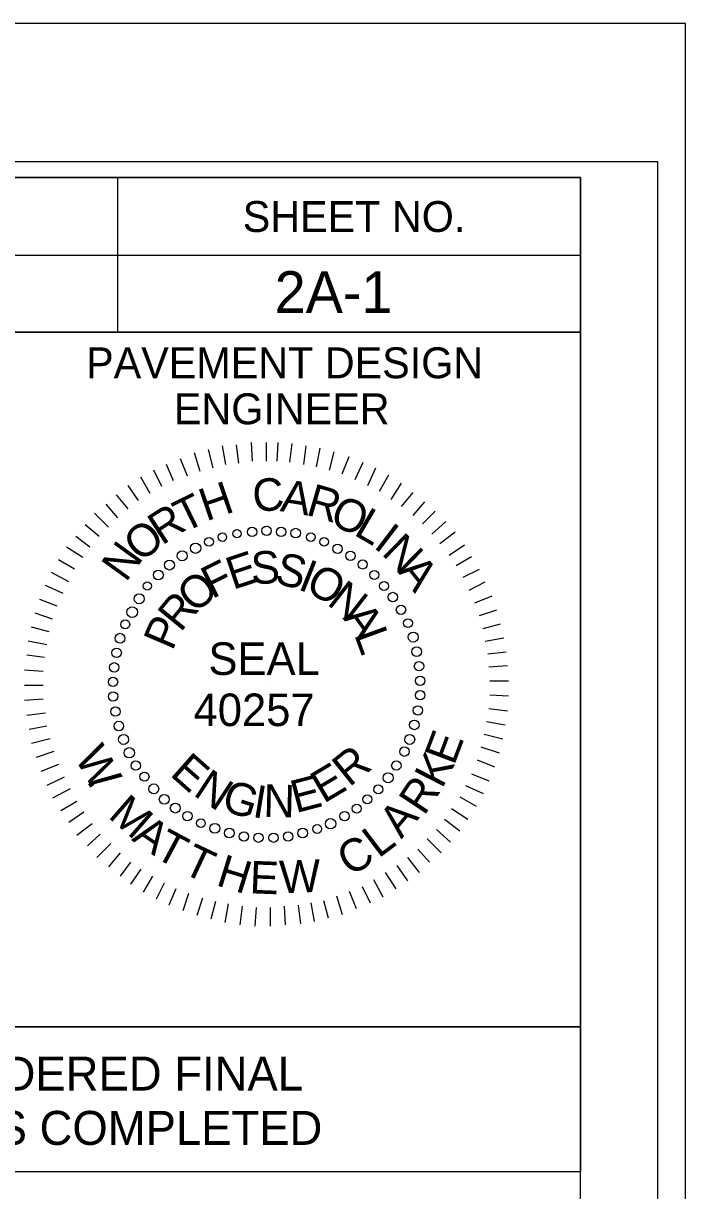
# Model space of a CAD drawing. Extents: x 2137858 to 2138172, y 2136084 to 2136289.
# Drawn here: x 2138152.47 to 2138172.48, y 2136253.7 to 2136289.01 of the extents above; entities that cross this region are included whole.
import ezdxf

# ---------------------------------------------------------------- set-up
doc = ezdxf.new("R2010")
doc.units = 0
for name, color, linetype in [('Default', 7, 'Continuous'), ('Sheet Cutting Line CELL', 7, 'Continuous'), ('Sheet Data Field CELL', 7, 'Continuous'), ('Sheet Plot Border Inside CELL', 7, 'Continuous'), ('Sheet Plot Border Outside CELL', 7, 'Continuous'), ('Sheet Sticker Exception Certification CELL', 7, 'Continuous'), ('Sheet Typical CELL', 7, 'Continuous')]:
    doc.layers.add(name, color=color, linetype=linetype)

msp = doc.modelspace()

# ---------------------------------------------------------------- linework, layer by layer
at = {"layer": 'Default'}
for p, q in [((2138159.889, 2136278.05), (2138159.889, 2136278.05)), ((2138159.398, 2136275.77), (2138159.363, 2136276.333)), ((2138159.82, 2136275.77), (2138159.82, 2136276.333)), ((2138160.136, 2136275.77), (2138160.172, 2136276.333)), ((2138160.523, 2136275.735), (2138160.593, 2136276.297)), ((2138157.816, 2136275.454), (2138157.64, 2136276.016)), ((2138158.203, 2136275.559), (2138158.062, 2136276.122)), ((2138158.589, 2136275.665), (2138158.484, 2136276.227)), ((2138158.976, 2136275.7), (2138158.906, 2136276.262)), ((2138160.945, 2136275.665), (2138161.015, 2136276.227)), ((2138161.332, 2136275.594), (2138161.437, 2136276.157)), ((2138161.718, 2136275.489), (2138161.859, 2136276.051)), ((2138157.007, 2136275.172), (2138156.797, 2136275.665)), ((2138157.429, 2136275.313), (2138157.218, 2136275.84)), ((2138162.105, 2136275.383), (2138162.316, 2136275.911)), ((2138162.492, 2136275.208), (2138162.738, 2136275.735)), ((2138156.304, 2136274.786), (2138156.023, 2136275.278)), ((2138156.656, 2136274.997), (2138156.41, 2136275.489)), ((2138162.879, 2136275.032), (2138163.125, 2136275.559)), ((2138163.23, 2136274.856), (2138163.511, 2136275.348)), ((2138155.953, 2136274.575), (2138155.636, 2136275.032)), ((2138163.582, 2136274.61), (2138163.898, 2136275.102)), ((2138155.636, 2136274.329), (2138155.285, 2136274.751)), ((2138163.898, 2136274.399), (2138164.25, 2136274.821)), ((2138164.25, 2136274.118), (2138164.601, 2136274.54)), ((2138155.039, 2136273.766), (2138154.617, 2136274.188)), ((2138155.32, 2136274.047), (2138154.968, 2136274.469)), ((2138164.531, 2136273.872), (2138164.918, 2136274.258)), ((2138154.757, 2136273.485), (2138154.336, 2136273.837)), ((2138164.812, 2136273.555), (2138165.234, 2136273.942)), ((2138154.476, 2136273.169), (2138154.054, 2136273.485)), ((2138165.058, 2136273.274), (2138165.515, 2136273.626)), ((2138154.265, 2136272.852), (2138153.773, 2136273.169)), ((2138165.34, 2136272.922), (2138165.797, 2136273.239)), ((2138154.019, 2136272.501), (2138153.527, 2136272.782)), ((2138165.55, 2136272.606), (2138166.008, 2136272.887)), ((2138165.761, 2136272.254), (2138166.254, 2136272.501)), ((2138153.843, 2136272.114), (2138153.316, 2136272.395)), ((2138165.937, 2136271.868), (2138166.429, 2136272.114)), ((2138153.668, 2136271.762), (2138153.14, 2136272.008)), ((2138166.113, 2136271.481), (2138166.64, 2136271.692)), ((2138153.492, 2136271.376), (2138152.964, 2136271.587)), ((2138153.351, 2136270.989), (2138152.824, 2136271.165)), ((2138166.254, 2136271.094), (2138166.781, 2136271.27)), ((2138153.246, 2136270.602), (2138152.718, 2136270.743)), ((2138166.359, 2136270.708), (2138166.886, 2136270.848)), ((2138153.175, 2136270.215), (2138152.613, 2136270.321)), ((2138166.429, 2136270.321), (2138166.992, 2136270.426)), ((2138166.5, 2136269.934), (2138167.062, 2136270.004)), ((2138153.105, 2136269.829), (2138152.578, 2136269.899)), ((2138166.535, 2136269.547), (2138167.097, 2136269.583)), ((2138153.07, 2136269.407), (2138152.507, 2136269.442)), ((2138153.07, 2136268.985), (2138152.507, 2136268.985)), ((2138159.82, 2136269.02), (2138159.82, 2136269.02)), ((2138166.57, 2136269.126), (2138167.133, 2136269.126)), ((2138153.07, 2136268.563), (2138152.507, 2136268.528)), ((2138166.57, 2136268.704), (2138167.133, 2136268.669)), ((2138166.535, 2136268.282), (2138167.097, 2136268.212)), ((2138153.14, 2136268.141), (2138152.578, 2136268.071)), ((2138166.465, 2136267.895), (2138167.027, 2136267.79)), ((2138153.175, 2136267.754), (2138152.648, 2136267.649)), ((2138166.394, 2136267.508), (2138166.957, 2136267.368)), ((2138153.281, 2136267.368), (2138152.718, 2136267.227)), ((2138166.289, 2136267.122), (2138166.851, 2136266.946)), ((2138153.386, 2136266.981), (2138152.859, 2136266.805)), ((2138153.527, 2136266.594), (2138153, 2136266.383)), ((2138166.183, 2136266.735), (2138166.711, 2136266.524)), ((2138153.703, 2136266.208), (2138153.175, 2136265.962)), ((2138166.008, 2136266.313), (2138166.535, 2136266.102)), ((2138153.879, 2136265.856), (2138153.351, 2136265.575)), ((2138165.832, 2136265.962), (2138166.359, 2136265.715)), ((2138154.089, 2136265.469), (2138153.597, 2136265.188)), ((2138165.656, 2136265.61), (2138166.148, 2136265.329)), ((2138154.3, 2136265.153), (2138153.843, 2136264.836)), ((2138165.41, 2136265.258), (2138165.902, 2136264.942)), ((2138154.546, 2136264.801), (2138154.089, 2136264.45)), ((2138165.199, 2136264.942), (2138165.656, 2136264.59)), ((2138154.793, 2136264.485), (2138154.406, 2136264.133)), ((2138164.672, 2136264.344), (2138165.093, 2136263.922)), ((2138164.953, 2136264.626), (2138165.375, 2136264.239)), ((2138155.109, 2136264.204), (2138154.687, 2136263.782)), ((2138164.39, 2136264.028), (2138164.742, 2136263.641)), ((2138155.39, 2136263.922), (2138155.039, 2136263.501)), ((2138155.707, 2136263.641), (2138155.39, 2136263.219)), ((2138164.074, 2136263.782), (2138164.425, 2136263.325)), ((2138156.023, 2136263.43), (2138155.707, 2136262.973)), ((2138156.375, 2136263.219), (2138156.093, 2136262.727)), ((2138163.406, 2136263.325), (2138163.722, 2136262.833)), ((2138163.758, 2136263.536), (2138164.074, 2136263.079)), ((2138156.726, 2136263.008), (2138156.48, 2136262.516)), ((2138162.703, 2136262.903), (2138162.949, 2136262.411)), ((2138163.054, 2136263.114), (2138163.336, 2136262.586)), ((2138157.078, 2136262.833), (2138156.867, 2136262.34)), ((2138157.464, 2136262.692), (2138157.289, 2136262.165)), ((2138157.886, 2136262.551), (2138157.711, 2136262.024)), ((2138161.929, 2136262.622), (2138162.105, 2136262.059)), ((2138162.316, 2136262.762), (2138162.527, 2136262.235)), ((2138158.273, 2136262.446), (2138158.132, 2136261.918)), ((2138158.66, 2136262.376), (2138158.554, 2136261.813)), ((2138159.082, 2136262.305), (2138159.011, 2136261.743)), ((2138159.504, 2136262.27), (2138159.468, 2136261.708)), ((2138159.925, 2136262.27), (2138159.925, 2136261.708)), ((2138160.347, 2136262.305), (2138160.382, 2136261.743)), ((2138160.769, 2136262.34), (2138160.839, 2136261.778)), ((2138161.156, 2136262.411), (2138161.261, 2136261.848)), ((2138161.543, 2136262.481), (2138161.683, 2136261.954))]:
    msp.add_line(p, q, dxfattribs=at)
for centre, radius in [((2138158.08, 2136273.327), 0.134), ((2138158.484, 2136273.467), 0.128), ((2138158.923, 2136273.573), 0.124), ((2138159.381, 2136273.626), 0.142), ((2138159.82, 2136273.661), 0.141), ((2138160.259, 2136273.626), 0.142), ((2138160.699, 2136273.59), 0.145), ((2138161.156, 2136273.467), 0.128), ((2138161.56, 2136273.327), 0.134), ((2138157.675, 2136273.133), 0.157), ((2138161.965, 2136273.116), 0.142), ((2138156.884, 2136272.624), 0.151), ((2138157.271, 2136272.905), 0.151), ((2138162.351, 2136272.905), 0.142), ((2138162.72, 2136272.641), 0.137), ((2138156.55, 2136272.325), 0.149), ((2138163.072, 2136272.325), 0.137), ((2138156.216, 2136271.991), 0.124), ((2138163.371, 2136271.991), 0.137), ((2138155.97, 2136271.604), 0.151), ((2138163.634, 2136271.657), 0.142), ((2138155.759, 2136271.2), 0.162), ((2138163.881, 2136271.27), 0.142), ((2138164.091, 2136270.866), 0.134), ((2138155.548, 2136270.831), 0.134), ((2138155.39, 2136270.409), 0.15), ((2138164.25, 2136270.444), 0.15), ((2138155.285, 2136269.969), 0.145), ((2138164.355, 2136270.004), 0.145), ((2138155.214, 2136269.53), 0.142), ((2138164.425, 2136269.565), 0.142), ((2138155.179, 2136269.09), 0.141), ((2138164.461, 2136269.126), 0.141), ((2138155.179, 2136268.651), 0.142), ((2138164.461, 2136268.686), 0.142), ((2138155.25, 2136268.194), 0.142), ((2138164.39, 2136268.229), 0.142), ((2138155.355, 2136267.754), 0.145), ((2138164.285, 2136267.79), 0.145), ((2138155.496, 2136267.35), 0.15), ((2138164.144, 2136267.35), 0.15), ((2138155.671, 2136266.946), 0.157), ((2138163.986, 2136266.981), 0.142), ((2138155.865, 2136266.559), 0.142), ((2138163.74, 2136266.559), 0.142), ((2138156.129, 2136266.225), 0.137), ((2138163.494, 2136266.19), 0.151), ((2138156.41, 2136265.856), 0.149), ((2138156.726, 2136265.54), 0.149), ((2138163.195, 2136265.838), 0.137), ((2138157.06, 2136265.276), 0.151), ((2138162.545, 2136265.258), 0.137), ((2138162.861, 2136265.54), 0.137), ((2138157.429, 2136265.03), 0.142), ((2138162.175, 2136265.03), 0.142), ((2138157.834, 2136264.819), 0.134), ((2138158.255, 2136264.661), 0.15), ((2138158.695, 2136264.52), 0.145), ((2138160.91, 2136264.52), 0.145), ((2138161.349, 2136264.643), 0.134), ((2138161.754, 2136264.801), 0.157), ((2138159.134, 2136264.415), 0.142), ((2138159.574, 2136264.379), 0.141), ((2138160.031, 2136264.379), 0.141), ((2138160.47, 2136264.415), 0.142)]:
    msp.add_circle(centre, radius, dxfattribs=at)
at = {"layer": 'Sheet Cutting Line CELL'}
msp.add_line((2138172.482, 2136289.006), (2137858.136, 2136289.006), dxfattribs=at)
at = {"layer": 'Sheet Plot Border Inside CELL'}
msp.add_lwpolyline([(2138171.642, 2136284.815), (2137860.562, 2136284.815), (2137860.562, 2136087.863), (2138171.642, 2136087.863)], close=True, dxfattribs=at)
at = {"layer": 'Sheet Plot Border Outside CELL'}
msp.add_lwpolyline([(2138172.482, 2136289.006), (2137858.136, 2136289.006), (2137858.136, 2136083.673), (2138172.482, 2136083.673)], close=True, dxfattribs=at)
at = {"layer": 'Sheet Sticker Exception Certification CELL'}
for p, q in [((2138131.966, 2136258.663), (2138169.309, 2136258.663)), ((2138169.309, 2136258.661), (2138169.309, 2136254.274)), ((2138169.309, 2136254.276), (2138131.966, 2136254.276))]:
    msp.add_line(p, q, dxfattribs=at)
at = {"layer": 'Sheet Typical CELL'}
for p, q in [((2138155.309, 2136284.33), (2138155.309, 2136279.663)), ((2138131.966, 2136281.997), (2138169.309, 2136281.997))]:
    msp.add_line(p, q, dxfattribs=at)
for points in [[(2138169.309, 2136284.339), (2137889.309, 2136284.339), (2137889.309, 2136088.339), (2138169.309, 2136088.339)], [(2138131.966, 2136284.339), (2138169.309, 2136284.339), (2138169.309, 2136279.663), (2138131.966, 2136279.663)], [(2138150.642, 2136279.663), (2138169.309, 2136279.663), (2138169.309, 2136258.663), (2138150.642, 2136258.663)]]:
    msp.add_lwpolyline(points, close=True, dxfattribs=at)

# ---------------------------------------------------------------- texts
at = {"layer": 'Default'}
for s, rotation, p in [('C', 4.8625, (2138159.433, 2136274.223)), ('H', 18.9162, (2138157.992, 2136273.942)), ('A', 350.8088, (2138160.207, 2136274.258)), ('R', 343.7819, (2138160.98, 2136274.153)), ('T', 25.943, (2138157.324, 2136273.59)), ('O', 336.7551, (2138161.683, 2136273.872)), ('R', 32.9699, (2138156.656, 2136273.204)), ('L', 329.7282, (2138162.422, 2136273.555)), ('O', 39.9967, (2138156.023, 2136272.676)), ('I', 322.7014, (2138163.019, 2136273.169)), ('N', 315.6745, (2138163.265, 2136272.958)), ('N', 54.0504, (2138155.566, 2136272.079)), ('F', 26.4777, (2138158.168, 2136271.587)), ('E', 18.4448, (2138158.8, 2136271.868)), ('S', 2.3789, (2138159.363, 2136272.044)), ('S', 346.313, (2138160.031, 2136272.079)), ('I', 338.28, (2138160.734, 2136271.903)), ('A', 308.6477, (2138163.758, 2136272.43)), ('O', 330.2471, (2138160.945, 2136271.868)), ('O', 42.5436, (2138157.675, 2136271.129)), ('N', 322.2141, (2138161.613, 2136271.446)), ('R', 50.5765, (2138157.218, 2136270.567)), ('P', 66.6424, (2138156.972, 2136270.004)), ('A', 306.1483, (2138162.105, 2136271.024)), ('L', 290.0824, (2138162.457, 2136270.532)), ('E', 69.3964, (2138165.485, 2136266.54)), ('W', 300.1025, (2138154.003, 2136266.804)), ('E', 318.5179, (2138156.867, 2136266.278)), ('R', 38.6997, (2138162.316, 2136265.891)), ('K', 62.9317, (2138165.122, 2136265.835)), ('N', 326.5361, (2138157.57, 2136265.68)), ('E', 30.6815, (2138161.543, 2136265.399)), ('.', 306.5672, (2138154.35, 2136266.089)), ('G', 342.5725, (2138158.414, 2136265.223)), ('E', 14.6452, (2138160.699, 2136265.118)), ('R', 56.467, (2138164.58, 2136265.018)), ('I', 350.5906, (2138159.363, 2136265.012)), ('N', 358.6088, (2138159.714, 2136265.012)), ('M', 318.9613, (2138155, 2136265.009)), ('A', 50.0023, (2138163.893, 2136264.321)), ('A', 325.426, (2138155.716, 2136264.312)), ('T', 331.8907, (2138156.379, 2136263.81)), ('L', 37.0729, (2138163.201, 2136263.739)), ('C', 30.6082, (2138162.333, 2136263.191)), ('T', 334.8907, (2138157.223, 2136263.334)), ('H', 342.8201, (2138158.26, 2136262.95)), ('E', 357.7495, (2138159.295, 2136262.699)), ('W', 2.2141, (2138160.223, 2136262.696))]:
    msp.add_text(s, height=0.984, rotation=rotation, dxfattribs=at).set_placement(p)
for s, p in [('SEAL', (2138158.062, 2136269.301)), ('40257', (2138157.611, 2136267.754))]:
    msp.add_text(s, height=0.9845, dxfattribs=at).set_placement(p)
at = {"layer": 'Sheet Data Field CELL'}
msp.add_text('2A-1', height=1.26, dxfattribs=at).set_placement((2138160.064, 2136280.251))
at = {"layer": 'Sheet Sticker Exception Certification CELL'}
for s, p in [('DOCUMENT NOT CONSIDERED FINAL', (2138135.9, 2136256.732)), ('UNLESS ALL SIGNATURES COMPLETED', (2138134.953, 2136255.089))]:
    msp.add_text(s, height=1.02673, dxfattribs=at).set_placement(p)
at = {"layer": 'Sheet Typical CELL'}
for s, height, p in [('SHEET NO.', 0.9334, (2138159.098, 2136282.697)), ('PAVEMENT DESIGN', 0.93335, (2138154.366, 2136278.273)), ('ENGINEER', 0.9334, (2138157.017, 2136276.882))]:
    msp.add_text(s, height=height, dxfattribs=at).set_placement(p)

doc.saveas('drawing.dxf')
